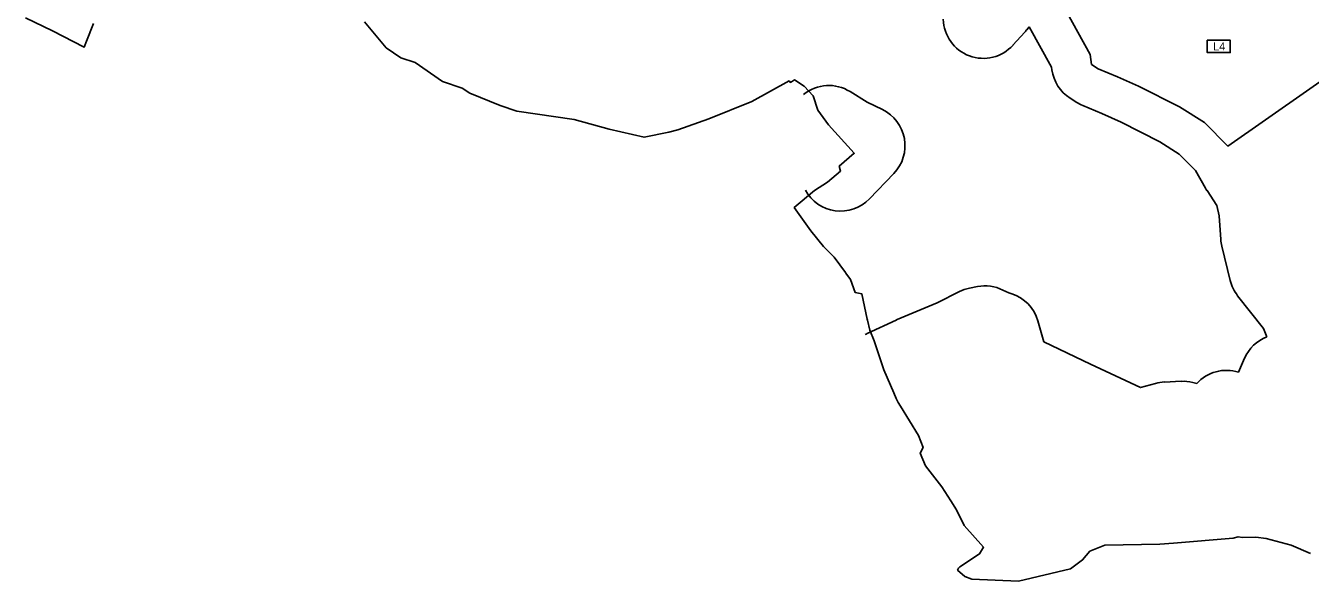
# Model space of a CAD drawing. Extents: x -547623 to -532764, y -1096714 to -1086523.
# Drawn here: x -545608 to -544003, y -1096472 to -1095778 of the extents above; entities that cross this region are included whole.
import ezdxf

# ---------------------------------------------------------------- set-up
doc = ezdxf.new("R2010")
doc.units = 0
for name, color, linetype in [('Vrstva 22', 7, 'Continuous'), ('Vrstva 23', 7, 'Continuous'), ('Vrstva 32', 7, 'Continuous'), ('Vrstva 36', 7, 'Continuous')]:
    doc.layers.add(name, color=color, linetype=linetype)

msp = doc.modelspace()

# ---------------------------------------------------------------- linework, layer by layer
at = {"layer": 'Vrstva 22'}
for points in [[(-545608, -1095768.4), (-545574.5, -1095784.4), (-545535, -1095804.9), (-545531.8, -1095797.3), (-545523.3, -1095775.1)], [(-545184.6, -1095773.1), (-545157.4, -1095805.8), (-545139.2, -1095818.1), (-545121.3, -1095824.1), (-545087, -1095847.9), (-545062.5, -1095856.1), (-545052.9, -1095862.3), (-545014.9, -1095877.9), (-544994.3, -1095884.9), (-544922.5, -1095895), (-544878.7, -1095907.3), (-544835.2, -1095917.4), (-544804.2, -1095911), (-544793.3, -1095907.9), (-544754.3, -1095894.2), (-544700.8, -1095872.9), (-544654.1, -1095846.9), (-544652.4, -1095848.8), (-544647.4, -1095845.7), (-544635.2, -1095853.4), (-544624, -1095865.8), (-544618.2, -1095883.4), (-544604.7, -1095901.8), (-544604.7, -1095901.8), (-544572.6, -1095937.4), (-544591.4, -1095953.3), (-544589.8, -1095959.6), (-544606.2, -1095973.6), (-544622.2, -1095984), (-544647.6, -1096005.3), (-544626.9, -1096034.1), (-544610.9, -1096053.7), (-544606.1, -1096058.8), (-544597.6, -1096067.2), (-544583.6, -1096086.4), (-544583.1, -1096087.1), (-544583.1, -1096087.1), (-544577.3, -1096095), (-544571.7, -1096111.2), (-544563.1, -1096113), (-544556.5, -1096144.4), (-544556.2, -1096145.9), (-544553.4, -1096158.2), (-544547.8, -1096171.8), (-544535.5, -1096208), (-544523.4, -1096236.5), (-544520.2, -1096243.7), (-544517.8, -1096248.6), (-544514.9, -1096253.3), (-544492.2, -1096290.1), (-544486.6, -1096305), (-544490.3, -1096311.9), (-544483.8, -1096327.7), (-544463.4, -1096354.1), (-544451.8, -1096371.7), (-544444.9, -1096382.8), (-544435.3, -1096402.4), (-544411.1, -1096429.4), (-544416.1, -1096437.8), (-544440.7, -1096453.9), (-544442.4, -1096455.7), (-544443.6, -1096458), (-544434.5, -1096466.1), (-544425.6, -1096469.5), (-544367.5, -1096472), (-544302.3, -1096456.3), (-544287.4, -1096445.3), (-544278.3, -1096434.5), (-544259.5, -1096426.9), (-544190.8, -1096425.7), (-544173.6, -1096424.2), (-544099.2, -1096418), (-544093, -1096416.6), (-544087.7, -1096417.3), (-544071, -1096417), (-544057.9, -1096418.4), (-544026.6, -1096427), (-544002.7, -1096437.1)]]:
    msp.add_lwpolyline(points, dxfattribs=at)
at = {"layer": 'Vrstva 23'}
for p, q in [((-544374.4, -1095802.3), (-544359.5, -1095785.9)), ((-544357.1, -1095783.1), (-544354.2, -1095779.3)), ((-544303, -1095868.5), (-544294.7, -1095873.8)), ((-544553.8, -1095994.3), (-544523.2, -1095962.6)), ((-544113.4, -1096053.2), (-544102.8, -1096096.3)), ((-544418.7, -1096103.9), (-544428.6, -1096105.9)), ((-544520.4, -1096145.8), (-544556.6, -1096162.6)), ((-544085, -1096193.5), (-544092.4, -1096210.8)), ((-544164.3, -1096222.2), (-544184.9, -1096223.1)), ((-544144.7, -1096225.1), (-544149.7, -1096223.7))]:
    msp.add_line(p, q, dxfattribs=at)
for points in [[(-544354.2, -1095779.3), (-544326.1, -1095830), (-544325.6, -1095833.1)], [(-544537.5, -1095882.9), (-544556.6, -1095873.7), (-544577.9, -1095860.3)], [(-544287, -1095877.8), (-544263.5, -1095887.6), (-544239, -1095898.6), (-544191, -1095923), (-544166.6, -1095938.4), (-544146.2, -1095958.9), (-544133.6, -1095981.1)], [(-544131.9, -1095983.9), (-544119.6, -1096002.6), (-544116.8, -1096015.5), (-544114.6, -1096045.1)], [(-544441.3, -1096110.2), (-544469.1, -1096124), (-544518.9, -1096145.2)], [(-544375.9, -1096112.9), (-544379.7, -1096111.7), (-544386.9, -1096108.2)], [(-544093.6, -1096115.3), (-544061.4, -1096156.3), (-544057, -1096166.5)], [(-544196.4, -1096224.9), (-544215.1, -1096230.1), (-544277.5, -1096201), (-544335.6, -1096172.9), (-544343.2, -1096146.6)]]:
    msp.add_lwpolyline(points, dxfattribs=at)
for centre, start, end in [((-544411.4, -1095768.8), 181.4263, 317.8953), ((-544396.6, -1095752.4), 317.8953, 322.1635), ((-544276.1, -1095826.4), 187.7959, 237.4708), ((-544604.4, -1095902.7), 57.9402, 129.0714), ((-544559.2, -1095927.9), 316.0396, 64.2789), ((-544267.8, -1095831.7), 237.4708, 247.3835), ((-544090.1, -1095956.4), 209.5862, 213.2655), ((-544589.8, -1095959.6), 208.6843, 316.0396), ((-544064.8, -1096041.4), 184.2338, 193.7352), ((-544419, -1096154.9), 101.1319, 116.5179), ((-544409.1, -1096153), 63.6095, 101.1319), ((-544054.3, -1096084.4), 193.7352, 218.1342), ((-544391.2, -1096160.5), 16.2249, 72.1988), ((-544499.4, -1096191.2), 112.9876, 114.8996), ((-544535.5, -1096208), 114.8996, 118.2281), ((-544039.1, -1096213.2), 111.0679, 156.8467), ((-544182.8, -1096273), 92.3605, 105.6828), ((-544162.2, -1096272.2), 75.553, 92.3605), ((-544107.5, -1096258.5), 72.4569, 138.0107)]:
    msp.add_arc(centre, 50, start, end, dxfattribs=at)
at = {"layer": 'Vrstva 32'}
msp.add_lwpolyline([(-544262.9, -1095672.3), (-544263.7, -1095671.7), (-544279.7, -1095660), (-544324.2, -1095659.4), (-544338.6, -1095662.6), (-544347, -1095680.5), (-544341.3, -1095691.5), (-544313.2, -1095741.8), (-544315.5, -1095746.1), (-544277.8, -1095813.9), (-544276.1, -1095826.4), (-544267.8, -1095831.7), (-544243.7, -1095841.7), (-544217.4, -1095853.4), (-544166.3, -1095879.5), (-544135.1, -1095899.1), (-544106, -1095928.4), (-543909.4, -1095790.9)], dxfattribs=at)
at = {"layer": 'Vrstva 36'}
msp.add_lwpolyline([(-544131.5, -1095796.2), (-544102.9, -1095796.2), (-544102.9, -1095811.7), (-544131.5, -1095811.7)], close=True, dxfattribs=at)

# ---------------------------------------------------------------- texts
msp.add_text('L4', height=10, dxfattribs=at).set_placement((-544124.1, -1095808.9))

doc.saveas('drawing.dxf')
